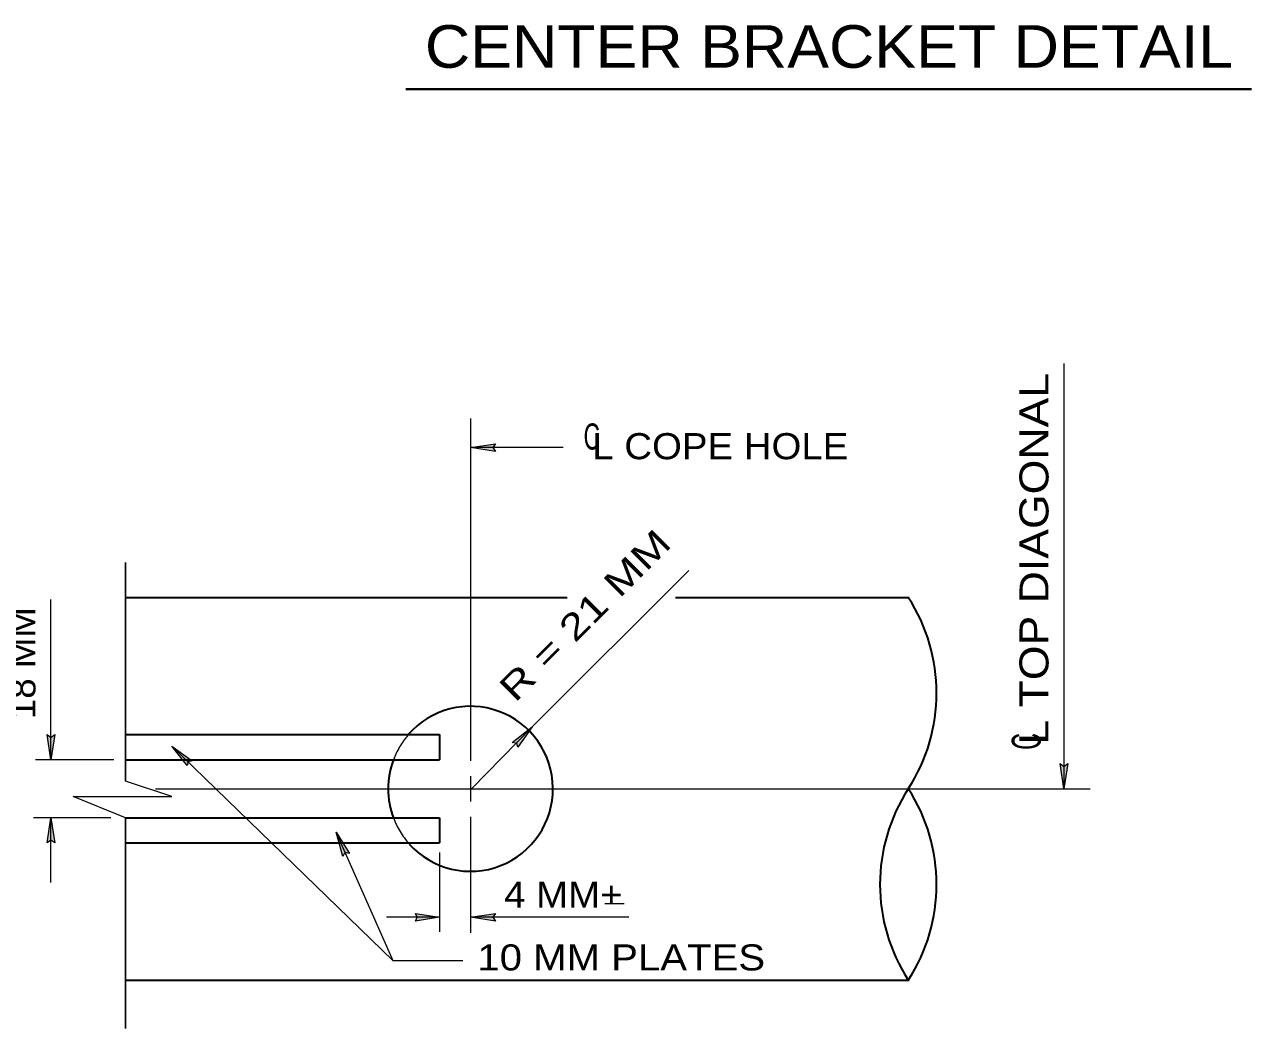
# Model space of a CAD drawing. Extents: x 312601.858 to 312602.699, y 144420.109 to 144420.704.
# Drawn here: x 312602.2782 to 312602.4051, y 144420.3959 to 144420.4998 of the extents above; entities that cross this region are included whole.
import ezdxf
from ezdxf.enums import TextEntityAlignment as Align

# ---------------------------------------------------------------- set-up
doc = ezdxf.new("R2010")
doc.units = 0
doc.header["$LTSCALE"] = 0.0012
doc.linetypes.add('DOT_DASHED', pattern=[7.7, 5, -1.2, 0.3, -1.2])
doc.linetypes.add('DOTTED', pattern=[1.5, 0.3, -1.2])
for name, color, linetype, lineweight in [('1', 7, 'Continuous', 25), ('2', 7, 'Continuous', 13), ('39', 7, 'Continuous', 13)]:
    doc.layers.add(name, color=color, linetype=linetype, lineweight=lineweight)

msp = doc.modelspace()

# ---------------------------------------------------------------- hatches: boundary and pattern name
at = {"layer": '39'}
for points in [[(312602.3266, 144420.456), (312602.3269, 144420.4556), (312602.3243, 144420.456), (312602.3269, 144420.4564)], [(312602.2809, 144420.426), (312602.2813, 144420.4263), (312602.2809, 144420.4237), (312602.2805, 144420.4263)], [(312602.2809, 144420.426), (312602.2813, 144420.4263), (312602.2809, 144420.4237), (312602.2805, 144420.4263)], [(312602.3291, 144420.4254), (312602.3286, 144420.4255), (312602.3307, 144420.4271), (312602.3292, 144420.425)], [(312602.2951, 144420.4235), (312602.295, 144420.4231), (312602.2934, 144420.4251), (312602.2955, 144420.4236)], [(312602.3857, 144420.423), (312602.3861, 144420.4233), (312602.3857, 144420.4207), (312602.3853, 144420.4233)], [(312602.2809, 144420.4154), (312602.2805, 144420.4151), (312602.2809, 144420.4177), (312602.2813, 144420.4151)], [(312602.2809, 144420.4154), (312602.2805, 144420.4151), (312602.2809, 144420.4177), (312602.2813, 144420.4151)], [(312602.3113, 144420.4141), (312602.3111, 144420.4137), (312602.3104, 144420.4162), (312602.3118, 144420.414)], [(312602.3188, 144420.4074), (312602.3186, 144420.4078), (312602.3211, 144420.4074), (312602.3186, 144420.407)], [(312602.3188, 144420.4074), (312602.3186, 144420.4078), (312602.3211, 144420.4074), (312602.3186, 144420.407)], [(312602.3266, 144420.4074), (312602.3269, 144420.407), (312602.3243, 144420.4074), (312602.3269, 144420.4078)], [(312602.3266, 144420.4074), (312602.3269, 144420.407), (312602.3243, 144420.4074), (312602.3269, 144420.4078)]]:
    msp.add_hatch(color=256, dxfattribs=at).paths.add_polyline_path(points)

# ---------------------------------------------------------------- linework, layer by layer
at = {"layer": '1', "lineweight": 13}
for p, q in [((312602.3857, 144420.4647), (312602.3857, 144420.4207)), ((312602.3243, 144420.459), (312602.3243, 144420.4236)), ((312602.3339, 144420.456), (312602.3244, 144420.456)), ((312602.2809, 144420.4237), (312602.2809, 144420.4403)), ((312602.3163, 144420.4029), (312602.2934, 144420.4251)), ((312602.2874, 144420.4237), (312602.2793, 144420.4237)), ((312602.3243, 144420.422), (312602.3243, 144420.4194)), ((312602.3825, 144420.4207), (312602.3884, 144420.4207)), ((312602.2871, 144420.4177), (312602.2791, 144420.4177)), ((312602.2809, 144420.411), (312602.2809, 144420.4177)), ((312602.3243, 144420.4178), (312602.3243, 144420.4058)), ((312602.3211, 144420.4141), (312602.3211, 144420.4059)), ((312602.3402, 144420.4088), (312602.3382, 144420.4088)), ((312602.3211, 144420.4074), (312602.3156, 144420.4074)), ((312602.3407, 144420.4074), (312602.3243, 144420.4074))]:
    msp.add_line(p, q, dxfattribs=at)
at = {"layer": '1'}
for p, q in [((312602.2886, 144420.4441), (312602.2886, 144420.4215)), ((312602.2886, 144420.4177), (312602.2886, 144420.3959))]:
    msp.add_line(p, q, dxfattribs=at)
at = {"layer": '1', "lineweight": 35}
for p, q in [((312602.2886, 144420.4405), (312602.3343, 144420.4405)), ((312602.3455, 144420.4405), (312602.3697, 144420.4405)), ((312602.3211, 144420.4263), (312602.3211, 144420.4237)), ((312602.2886, 144420.4237), (312602.3211, 144420.4237)), ((312602.2886, 144420.4177), (312602.3211, 144420.4177)), ((312602.2886, 144420.4177), (312602.3211, 144420.4177)), ((312602.3211, 144420.4177), (312602.3211, 144420.4151)), ((312602.2886, 144420.4151), (312602.3211, 144420.4151)), ((312602.2886, 144420.4009), (312602.3697, 144420.4009))]:
    msp.add_line(p, q, dxfattribs=at)
at = {"layer": '1', "linetype": 'DOT_DASHED', "lineweight": 13}
msp.add_line((312602.2917, 144420.4207), (312602.3865, 144420.4207), dxfattribs=at)
at = {"layer": '1', "lineweight": 13}
for points in [[(312602.3244, 144420.4207), (312602.3307, 144420.4271), (312602.3469, 144420.4433)], [(312602.2886, 144420.4177), (312602.2832, 144420.4199), (312602.2934, 144420.4199), (312602.2886, 144420.4215)], [(312602.3235, 144420.4029), (312602.3163, 144420.4029), (312602.3104, 144420.4162)]]:
    msp.add_lwpolyline(points, dxfattribs=at)
at = {"layer": '1', "lineweight": 35}
msp.add_lwpolyline([(312602.2886, 144420.4263), (312602.3183, 144420.4263), (312602.3211, 144420.4263)], dxfattribs=at)
for centre, radius, start, end in [((312602.354343, 144420.4306), 0.018187, 327.02071, 32.97929), ((312602.3243, 144420.4207), 0.008538, 222.13874, 139.01418), ((312602.3243, 144420.4207), 0.008515, 159.44396, 200.79411), ((312602.384857, 144420.4108), 0.018187, 147.02071, 212.97929), ((312602.354343, 144420.4108), 0.018187, 327.02071, 32.97929)]:
    msp.add_arc(centre, radius, start, end, dxfattribs=at)
at = {"layer": '1', "linetype": 'DOTTED', "lineweight": 13}
for start, end in [(139.4749, 159.44396), (200.55604, 222.08916)]:
    msp.add_arc((312602.3243, 144420.4207), 0.008515, start, end, dxfattribs=at)
at = {"layer": '2', "lineweight": 40}
msp.add_line((312602.3176, 144420.4931), (312602.4051, 144420.4931), dxfattribs=at)
at = {"layer": '39'}
for points in [[(312602.3266, 144420.456), (312602.3269, 144420.4556), (312602.3243, 144420.456), (312602.3269, 144420.4564)], [(312602.2809, 144420.426), (312602.2813, 144420.4263), (312602.2809, 144420.4237), (312602.2805, 144420.4263)], [(312602.2809, 144420.426), (312602.2813, 144420.4263), (312602.2809, 144420.4237), (312602.2805, 144420.4263)], [(312602.3291, 144420.4254), (312602.3286, 144420.4255), (312602.3307, 144420.4271), (312602.3292, 144420.425)], [(312602.2951, 144420.4235), (312602.295, 144420.4231), (312602.2934, 144420.4251), (312602.2955, 144420.4236)], [(312602.3857, 144420.423), (312602.3861, 144420.4233), (312602.3857, 144420.4207), (312602.3853, 144420.4233)], [(312602.2809, 144420.4154), (312602.2805, 144420.4151), (312602.2809, 144420.4177), (312602.2813, 144420.4151)], [(312602.2809, 144420.4154), (312602.2805, 144420.4151), (312602.2809, 144420.4177), (312602.2813, 144420.4151)], [(312602.3113, 144420.4141), (312602.3111, 144420.4137), (312602.3104, 144420.4162), (312602.3118, 144420.414)], [(312602.3188, 144420.4074), (312602.3186, 144420.4078), (312602.3211, 144420.4074), (312602.3186, 144420.407)], [(312602.3188, 144420.4074), (312602.3186, 144420.4078), (312602.3211, 144420.4074), (312602.3186, 144420.407)], [(312602.3266, 144420.4074), (312602.3269, 144420.407), (312602.3243, 144420.4074), (312602.3269, 144420.4078)], [(312602.3266, 144420.4074), (312602.3269, 144420.407), (312602.3243, 144420.4074), (312602.3269, 144420.4078)]]:
    msp.add_lwpolyline(points, close=True, dxfattribs=at)

# ---------------------------------------------------------------- texts
at = {"layer": '1', "width": 1.05}
msp.add_text('18 MM', height=0.0027, rotation=90, dxfattribs=at).set_placement((312602.2793, 144420.4337), align=Align.CENTER)
at = {"layer": '2'}
for s, height, width, p in [('CENTER BRACKET DETAIL', 0.00441, 1.1, (312602.3614, 144420.4953)), ('C', 0.0027, 0.65, (312602.33685, 144420.4558)), ('L COPE HOLE', 0.0027, 1.1, (312602.35015, 144420.4548)), ('4 MM+', 0.0027, 1.1, (312602.3339, 144420.4084)), ('10 MM PLATES', 0.0027, 1.15, (312602.3399, 144420.4019))]:
    msp.add_text(s, height=height, dxfattribs=dict(at, width=width)).set_placement(p, align=Align.CENTER)
for s, height, rotation, width, p in [('L TOP DIAGONAL', 0.003, 90, 1.15, (312602.3841, 144420.4445)), ('R = 21 MM', 0.0027, 45, 1.3, (312602.337095, 144420.437695)), ('C', 0.003, 90, 0.6, (312602.3833, 144420.4256))]:
    msp.add_text(s, height=height, rotation=rotation, dxfattribs=dict(at, width=width)).set_placement(p, align=Align.CENTER)

doc.saveas('drawing.dxf')
